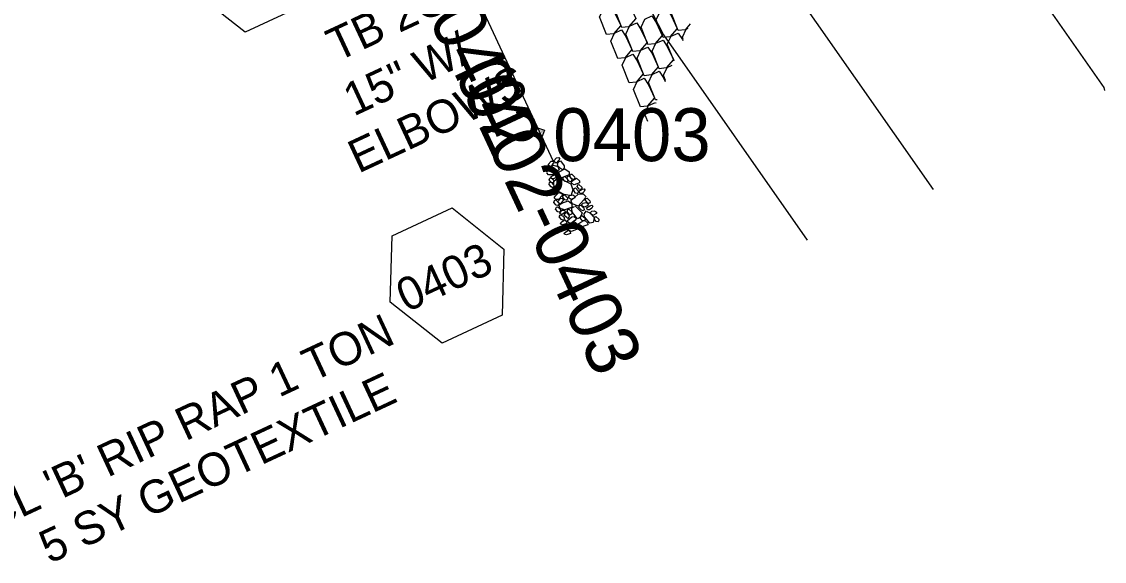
# Model space of a CAD drawing. Extents: x 2321431 to 2321984, y 922046 to 922317.
# Drawn here: x 2321522.3 to 2321686, y 922046.5 to 922128 of the extents above; entities that cross this region are included whole.
import ezdxf

# ---------------------------------------------------------------- set-up
doc = ezdxf.new("R2010")
doc.units = 0
for name, color, linetype in [('Exist Hydrographic Top of Bank', 7, 'Continuous'), ('Prop Boundary Buffer Zone 1', 7, 'Continuous'), ('Prop Boundary Buffer Zone 2', 7, 'Continuous'), ('Prop Drainage Structure Box Number Symbol CELL', 7, 'Continuous'), ('Prop Drainage Structure Drop Inlet Grate 2 Narrow Slots and Flat Grates 840 29 TB Label', 7, 'Continuous'), ('Prop Drainage Structure Pipe Alternate 15in', 7, 'Continuous'), ('Prop Drainage Structure Pipe Alternate 15in Label', 7, 'Continuous'), ('Prop Drainage Structure Pipe Elbow Alternate CELL', 7, 'Continuous'), ('Prop Erosion Rip Rap Pad at Outlet CELL', 7, 'Continuous'), ('Prop Erosion Rip Rap Pad at Outlet Label', 7, 'Continuous'), ('Prop Plan Preparation Excavation Hatching', 7, 'Continuous'), ('Scratch_Level_0', 7, 'Continuous')]:
    doc.layers.add(name, color=color, linetype=linetype)

msp = doc.modelspace()

# ---------------------------------------------------------------- linework, layer by layer
at = {"layer": 'Exist Hydrographic Top of Bank'}
msp.add_lwpolyline([(2321611.12, 922253.52), (2321614.15, 922245.97), (2321638.35, 922202.81), (2321649, 922182.15), (2321651.57, 922172.91), (2321662.29, 922151.88), (2321685.95, 922118.11), (2321686.02, 922117.66)], dxfattribs=at)
at = {"layer": 'Prop Boundary Buffer Zone 1'}
msp.add_lwpolyline([(2321632.27, 922144.71), (2321636.52, 922136.38), (2321660.14, 922102.66)], dxfattribs=at)
at = {"layer": 'Prop Boundary Buffer Zone 2'}
msp.add_lwpolyline([(2321613.73, 922137.05), (2321619.33, 922126.05), (2321641.07, 922095.04)], dxfattribs=at)
at = {"layer": 'Prop Drainage Structure Box Number Symbol CELL'}
for points in [[(2321548.51, 922142.64), (2321557.57, 922146.87), (2321565.4, 922140.65), (2321565.13, 922130.65), (2321556.07, 922126.43), (2321548.23, 922132.65), (2321548.51, 922142.64)], [(2321578.32, 922095.66), (2321587.38, 922099.88), (2321595.21, 922093.67), (2321594.94, 922083.67), (2321585.88, 922079.45), (2321578.04, 922085.66), (2321578.32, 922095.66)]]:
    msp.add_lwpolyline(points, dxfattribs=at)
at = {"layer": 'Prop Drainage Structure Pipe Alternate 15in'}
msp.add_line((2321587.05, 922140.5), (2321602.68, 922106.96), dxfattribs=at)
at = {"layer": 'Prop Drainage Structure Pipe Elbow Alternate CELL'}
msp.add_line((2321600.63, 922111.29), (2321600.63, 922111.29), dxfattribs=at)
msp.add_line((2321600.63, 922111.29), (2321600.63, 922111.29), dxfattribs=at)
msp.add_lwpolyline([(2321599.92, 922110.96), (2321600.3, 922112.01), (2321601.35, 922111.63), (2321600.97, 922110.58), (2321599.92, 922110.96)], dxfattribs=at)
at = {"layer": 'Prop Erosion Rip Rap Pad at Outlet CELL'}
msp.add_line((2321602.68, 922106.96), (2321602.68, 922106.96), dxfattribs=at)
msp.add_line((2321602.68, 922106.96), (2321602.68, 922106.96), dxfattribs=at)
for points in [[(2321602.8, 922106.69), (2321602.64, 922106.53), (2321602.3, 922106.11), (2321602, 922106.29), (2321601.92, 922106.46), (2321602.34, 922106.97), (2321602.68, 922106.96), (2321602.8, 922106.69)], [(2321603.66, 922107.25), (2321603.49, 922107.08), (2321603.12, 922106.64), (2321602.85, 922106.85), (2321602.76, 922107.02), (2321603.17, 922107.48), (2321603.52, 922107.52), (2321603.66, 922107.25)], [(2321604.06, 922105.66), (2321603.76, 922105.85), (2321603.3, 922106.29), (2321603.42, 922106.81), (2321603.78, 922106.99), (2321604.35, 922106.27), (2321604.31, 922105.92), (2321604.06, 922105.66)], [(2321601.65, 922105.31), (2321601.94, 922105.65), (2321602.68, 922106.36), (2321603.37, 922106.15), (2321603.56, 922105.65), (2321602.62, 922104.87), (2321601.98, 922104.88), (2321601.71, 922105.2)], [(2321602.35, 922104.64), (2321602.55, 922104.75), (2321602.95, 922104.95), (2321603.19, 922104.73), (2321603.27, 922104.56), (2321602.73, 922104.3), (2321602.37, 922104.36), (2321602.35, 922104.64)], [(2321603.16, 922105.05), (2321603.55, 922105.37), (2321604.45, 922105.82), (2321605.07, 922105.36), (2321605.07, 922104.91), (2321603.93, 922104.43), (2321603.38, 922104.63), (2321603.16, 922105.05)], [(2321605.8, 922104.21), (2321605.51, 922104.27), (2321605.2, 922104.66), (2321605.29, 922104.97), (2321605.48, 922105.01), (2321605.9, 922104.59), (2321605.92, 922104.39), (2321605.8, 922104.21)], [(2321602.63, 922102.94), (2321602.36, 922103.06), (2321602.04, 922103.45), (2321602.11, 922103.73), (2321602.32, 922103.83), (2321602.76, 922103.35), (2321602.76, 922103.12), (2321602.63, 922102.94)], [(2321602.64, 922103.66), (2321602.37, 922103.73), (2321602.05, 922104.12), (2321602.15, 922104.41), (2321602.32, 922104.49), (2321602.78, 922104.06), (2321602.78, 922103.81), (2321602.64, 922103.66)], [(2321605.19, 922101.79), (2321604.34, 922101.92), (2321602.8, 922102.73), (2321602.79, 922103.94), (2321603.4, 922104.5), (2321605.34, 922103.54), (2321605.66, 922102.61), (2321605.34, 922101.72)], [(2321604.74, 922103.84), (2321604.46, 922103.9), (2321604.15, 922104.3), (2321604.23, 922104.6), (2321604.42, 922104.64), (2321604.85, 922104.22), (2321604.86, 922104.02), (2321604.74, 922103.84)], [(2321605.33, 922103.84), (2321605.03, 922103.95), (2321604.76, 922104.35), (2321604.82, 922104.64), (2321605.03, 922104.73), (2321605.48, 922104.24), (2321605.45, 922104.02), (2321605.33, 922103.84)], [(2321605.37, 922103.83), (2321605.68, 922104.11), (2321606.21, 922104.38), (2321606.65, 922104.01), (2321606.64, 922103.67), (2321605.83, 922103.37), (2321605.49, 922103.57), (2321605.37, 922103.83)], [(2321606.88, 922102.65), (2321606.6, 922102.72), (2321606.29, 922103.12), (2321606.38, 922103.4), (2321606.56, 922103.45), (2321606.99, 922103.04), (2321607, 922102.84), (2321606.88, 922102.65)], [(2321602.37, 922102.13), (2321602.6, 922102.33), (2321603.02, 922102.58), (2321603.27, 922102.33), (2321603.32, 922102.06), (2321602.72, 922101.85), (2321602.42, 922101.95), (2321602.37, 922102.13)], [(2321602.84, 922101.4), (2321603.01, 922101.72), (2321603.53, 922102.2), (2321603.96, 922102.07), (2321604.09, 922101.8), (2321603.49, 922101.16), (2321603.06, 922101.17), (2321602.84, 922101.4)], [(2321604.68, 922101.04), (2321604.41, 922101.09), (2321604.12, 922101.51), (2321604.18, 922101.79), (2321604.38, 922101.88), (2321604.82, 922101.44), (2321604.82, 922101.19), (2321604.68, 922101.04)], [(2321605, 922101.55), (2321605.21, 922101.79), (2321605.63, 922101.87), (2321605.95, 922101.65), (2321605.93, 922101.43), (2321605.39, 922101.17), (2321605.07, 922101.38), (2321605, 922101.55)], [(2321607.55, 922101.48), (2321607.25, 922101.04), (2321606.46, 922100.15), (2321605.58, 922100.51), (2321605.36, 922100.94), (2321606.45, 922101.95), (2321607.21, 922102), (2321607.66, 922101.55)], [(2321606.32, 922102.05), (2321606.06, 922102.14), (2321605.78, 922102.53), (2321605.85, 922102.83), (2321606.05, 922102.92), (2321606.46, 922102.45), (2321606.44, 922102.23), (2321606.32, 922102.05)], [(2321607.46, 922102.61), (2321607.37, 922102.37), (2321607.05, 922102.08), (2321606.7, 922102.12), (2321606.55, 922102.41), (2321607.06, 922102.74), (2321607.37, 922102.78), (2321607.46, 922102.61)], [(2321603.38, 922100.25), (2321603.1, 922100.32), (2321602.78, 922100.71), (2321602.89, 922101.01), (2321603.06, 922101.09), (2321603.52, 922100.65), (2321603.52, 922100.4), (2321603.38, 922100.25)], [(2321603.64, 922099.25), (2321603.36, 922099.31), (2321603.04, 922099.7), (2321603.15, 922100), (2321603.32, 922100.08), (2321603.79, 922099.64), (2321603.78, 922099.39), (2321603.64, 922099.25)], [(2321604.25, 922101.11), (2321604.1, 922100.92), (2321603.75, 922100.52), (2321603.43, 922100.73), (2321603.36, 922100.88), (2321603.8, 922101.35), (2321604.02, 922101.34), (2321604.25, 922101.11)], [(2321603.54, 922100.3), (2321603.96, 922100.62), (2321604.91, 922100.98), (2321605.45, 922100.57), (2321605.52, 922100.03), (2321604.41, 922099.59), (2321603.71, 922099.8), (2321603.54, 922100.3)], [(2321605.98, 922100.2), (2321606.32, 922099.92), (2321607.04, 922099.14), (2321606.82, 922098.49), (2321606.35, 922098.26), (2321605.59, 922099.22), (2321605.45, 922099.83), (2321605.9, 922100.12)], [(2321607.18, 922099.47), (2321606.94, 922099.54), (2321606.55, 922099.96), (2321606.66, 922100.25), (2321606.85, 922100.3), (2321607.31, 922099.87), (2321607.33, 922099.67), (2321607.18, 922099.47)], [(2321606.98, 922100.39), (2321607.2, 922100.63), (2321607.62, 922100.71), (2321607.94, 922100.49), (2321607.92, 922100.28), (2321607.38, 922100.01), (2321607.06, 922100.22), (2321606.98, 922100.39)], [(2321608.13, 922100.58), (2321607.85, 922100.64), (2321607.54, 922101.04), (2321607.62, 922101.34), (2321607.8, 922101.38), (2321608.23, 922100.97), (2321608.25, 922100.78), (2321608.13, 922100.58)], [(2321608.68, 922100.16), (2321608.53, 922099.85), (2321608.17, 922099.58), (2321607.85, 922099.62), (2321607.71, 922099.89), (2321608.22, 922100.22), (2321608.52, 922100.29), (2321608.68, 922100.16)], [(2321604.22, 922098), (2321603.93, 922098.15), (2321603.59, 922098.53), (2321603.71, 922098.8), (2321603.87, 922098.87), (2321604.35, 922098.43), (2321604.34, 922098.18), (2321604.22, 922098)], [(2321604.57, 922099.35), (2321604.41, 922099.19), (2321604.02, 922098.88), (2321603.72, 922098.98), (2321603.65, 922099.11), (2321603.99, 922099.53), (2321604.31, 922099.56), (2321604.49, 922099.44)], [(2321604.88, 922098.28), (2321604.73, 922098.42), (2321604.33, 922098.77), (2321604.5, 922099.11), (2321604.67, 922099.19), (2321605.16, 922098.71), (2321605.03, 922098.48), (2321604.88, 922098.28)], [(2321605.38, 922098.87), (2321605.07, 922098.96), (2321604.76, 922099.36), (2321604.87, 922099.65), (2321605.05, 922099.71), (2321605.47, 922099.29), (2321605.5, 922099.05), (2321605.38, 922098.87)], [(2321606.17, 922098.29), (2321605.94, 922097.98), (2321605.36, 922097.55), (2321604.96, 922097.69), (2321604.83, 922097.97), (2321605.47, 922098.53), (2321605.85, 922098.59), (2321606.17, 922098.29)], [(2321607.35, 922097.93), (2321607.06, 922098), (2321606.73, 922098.38), (2321606.84, 922098.68), (2321607.01, 922098.76), (2321607.48, 922098.32), (2321607.48, 922098.07), (2321607.35, 922097.93)], [(2321607.76, 922099.37), (2321608.21, 922099.14), (2321608.92, 922098.4), (2321608.72, 922097.71), (2321608.19, 922097.59), (2321607.38, 922098.52), (2321607.36, 922099.01), (2321607.73, 922099.44)], [(2321608.27, 922099.16), (2321608.5, 922099.39), (2321608.91, 922099.47), (2321609.23, 922099.24), (2321609.2, 922099.03), (2321608.67, 922098.76), (2321608.35, 922098.99), (2321608.27, 922099.16)], [(2321609.45, 922097.79), (2321609.16, 922097.85), (2321608.85, 922098.24), (2321608.95, 922098.55), (2321609.13, 922098.59), (2321609.56, 922098.18), (2321609.57, 922097.98), (2321609.45, 922097.79)], [(2321603.76, 922096.92), (2321604, 922097.12), (2321604.42, 922097.37), (2321604.66, 922097.12), (2321604.72, 922096.85), (2321604.11, 922096.64), (2321603.82, 922096.74), (2321603.76, 922096.92)], [(2321603.79, 922097.6), (2321604.02, 922097.82), (2321604.44, 922098.07), (2321604.68, 922097.81), (2321604.74, 922097.55), (2321604.13, 922097.34), (2321603.84, 922097.43), (2321603.79, 922097.6)], [(2321604.62, 922097.03), (2321605.05, 922097.32), (2321605.91, 922097.78), (2321606.53, 922097.3), (2321606.55, 922096.77), (2321605.44, 922096.31), (2321604.85, 922096.56), (2321604.62, 922097.03)], [(2321606.55, 922097.53), (2321606.85, 922097.75), (2321607.42, 922098.03), (2321607.84, 922097.64), (2321607.89, 922097.35), (2321607, 922097.03), (2321606.66, 922097.21), (2321606.55, 922097.53)], [(2321604.33, 922096.08), (2321604.57, 922096.29), (2321604.99, 922096.54), (2321605.23, 922096.28), (2321605.29, 922096.01), (2321604.68, 922095.8), (2321604.39, 922095.9), (2321604.33, 922096.08)]]:
    msp.add_lwpolyline(points, dxfattribs=at)
at = {"layer": 'Prop Plan Preparation Excavation Hatching'}
msp.add_line((2321618.12, 922115.84), (2321618.19, 922115.74), dxfattribs=at)
for points in [[(2321613.6, 922131.5), (2321614.24, 922130.5), (2321615.16, 922128.53), (2321614.08, 922127.28), (2321613.03, 922127.16), (2321611.97, 922129.82), (2321612.53, 922131), (2321613.6, 922131.5)], [(2321623.37, 922127.69), (2321622.61, 922126.82), (2321621.56, 922126.7), (2321620.5, 922129.35), (2321621.07, 922130.54), (2321622.13, 922131.03)], [(2321611.32, 922130.44), (2321611.96, 922129.44), (2321612.88, 922127.47), (2321611.8, 922126.22), (2321610.75, 922126.1), (2321609.69, 922128.75), (2321610.26, 922129.94), (2321611.32, 922130.44)], [(2321619.85, 922129.97), (2321620.5, 922128.98), (2321621.42, 922127.01), (2321620.33, 922125.75), (2321619.28, 922125.64), (2321618.22, 922128.29), (2321618.79, 922129.48), (2321619.85, 922129.97)], [(2321615.3, 922127.85), (2321615.94, 922126.85), (2321616.86, 922124.88), (2321615.78, 922123.63), (2321614.73, 922123.52), (2321613.67, 922126.17), (2321614.23, 922127.35), (2321615.3, 922127.85)], [(2321617.58, 922128.91), (2321618.22, 922127.92), (2321619.14, 922125.94), (2321618.05, 922124.69), (2321617, 922124.58), (2321615.95, 922127.23), (2321616.51, 922128.42), (2321617.58, 922128.91)], [(2321613.02, 922126.79), (2321613.67, 922125.79), (2321614.58, 922123.82), (2321613.5, 922122.57), (2321612.45, 922122.45), (2321611.39, 922125.11), (2321611.96, 922126.29), (2321613.02, 922126.79)], [(2321620.94, 922122.09), (2321619.92, 922124.64), (2321620.49, 922125.83), (2321621.55, 922126.32)], [(2321621.55, 922126.32), (2321622.2, 922125.33), (2321622.27, 922125.17)], [(2321622.35, 922125.34), (2321622.2, 922125.7), (2321622.77, 922126.89), (2321623.08, 922127.04)], [(2321619.28, 922125.26), (2321619.92, 922124.27), (2321620.84, 922122.3), (2321619.75, 922121.04), (2321618.7, 922120.93), (2321617.65, 922123.58), (2321618.21, 922124.77), (2321619.28, 922125.26)], [(2321614.72, 922123.14), (2321615.37, 922122.14), (2321616.28, 922120.17), (2321615.2, 922118.92), (2321614.15, 922118.81), (2321613.09, 922121.46), (2321613.66, 922122.64), (2321614.72, 922123.14)], [(2321617, 922124.2), (2321617.64, 922123.21), (2321618.56, 922121.23), (2321617.48, 922119.98), (2321616.43, 922119.87), (2321615.37, 922122.52), (2321615.93, 922123.71), (2321617, 922124.2)], [(2321619.66, 922119.14), (2321619.35, 922119.93), (2321619.91, 922121.12), (2321620.68, 922121.47)], [(2321616.42, 922119.49), (2321617.07, 922118.5), (2321617.99, 922116.52), (2321616.9, 922115.27), (2321615.85, 922115.16), (2321614.79, 922117.81), (2321615.36, 922119), (2321616.42, 922119.49)], [(2321618.41, 922116.25), (2321618.13, 922116.22), (2321617.07, 922118.87), (2321617.63, 922120.06), (2321618.7, 922120.55)], [(2321618.7, 922120.55), (2321619.34, 922119.56), (2321619.6, 922119)], [(2321616.98, 922112.94), (2321616.49, 922114.16), (2321617.06, 922115.35), (2321618.12, 922115.84)]]:
    msp.add_lwpolyline(points, dxfattribs=at)

# ---------------------------------------------------------------- texts
at = {"layer": 'Prop Drainage Structure Box Number Symbol CELL'}
msp.add_text('0403', height=5, rotation=24.9913, dxfattribs=at).set_placement((2321580.48, 922084.04))
at = {"layer": 'Prop Drainage Structure Drop Inlet Grate 2 Narrow Slots and Flat Grates 840 29 TB Label'}
msp.add_text('TB 2GI', height=5, rotation=24.9913, dxfattribs=at).set_placement((2321569.96, 922121.92))
at = {"layer": 'Prop Drainage Structure Pipe Alternate 15in Label'}
for s, p in [('15" W/', (2321572.49, 922113.68)), ('ELBOWS', (2321573.21, 922105.05))]:
    msp.add_text(s, height=5, rotation=24.9913, dxfattribs=at).set_placement(p)
at = {"layer": 'Prop Drainage Structure Pipe Elbow Alternate CELL'}
msp.add_text('ELB', height=0.36, rotation=24.9913, dxfattribs=at).set_placement((2321600.31, 922110.98))
at = {"layer": 'Prop Erosion Rip Rap Pad at Outlet Label'}
for s, p in [("CL 'B' RIP RAP 1 TON", (2321517.8, 922050.97)), ('5 SY GEOTEXTILE', (2321526.49, 922046.06))]:
    msp.add_text(s, height=5, rotation=24.9913, dxfattribs=at).set_placement(p)
at = {"layer": 'Scratch_Level_0'}
for s, p in [('0401-0402', (2321572.19, 922153.43)), ('0402-0403', (2321587.61, 922120.35))]:
    msp.add_text(s, height=8, rotation=294.9913, dxfattribs=at).set_placement(p)
msp.add_text('0403', height=8, dxfattribs=at).set_placement((2321602.68, 922106.96))

doc.saveas('drawing.dxf')
